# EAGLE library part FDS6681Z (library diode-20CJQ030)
Fairchild's FDS6681Z 30 Volt P-Channel PowerTrench® MOSFET General Description This P-Channel MOSFET is produced using Fairchild Semiconductor's advanced PowerTrench® process that has been especially tailored to minimize the on-state resistance. This device is well suited for Power Management and load switching applications common in Notebook Computers and Portable Battery Packs. Features: -20 A, -30 V. RDS(ON) = 4.6 mOhm @ VGS = -10 V RDS(ON) = 6.5 mOhm @ VGS = -4.5 V Extended VGSS range (-25V) for battery applications HBM ESD protection level of 8kV typical (note 3) High performance trench technology for extremely low RDS(ON) High power and current handling capability Termination is Lead-free and RoHS Compliant Please send any comments to: messi@users.sourceforge.net
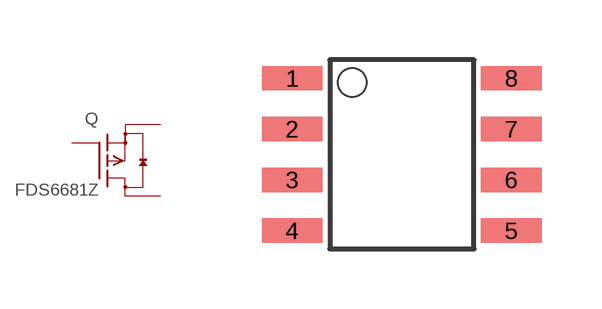
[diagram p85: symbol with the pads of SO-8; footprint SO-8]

Designator prefix Q

## FDS6681Z  [SO-8]
1  S  pas
2  S  pas
3  S  pas
4  G  pas
5  D  pas
6  D  pas
7  D  pas
8  D  pas

## Footprint SO-8 (pad centres in mm)
small outline
smd 1.524 x 0.61: 1 -2.743,1.27; 2 -2.743,0; 3 -2.743,-1.27; 4 -2.743,-2.54; 5 2.743,-2.54; 6 2.743,-1.27; 7 2.743,0; 8 2.743,1.27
